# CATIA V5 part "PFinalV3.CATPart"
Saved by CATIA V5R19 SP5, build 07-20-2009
Part number: PeçaFinal
Bounding box of the stored display mesh (mm): x -39 to 2, y -77 to 65.5, z -65.329 to 80.065
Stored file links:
  Z:\UA\ATLAS\atlascar\ServoPiloto\dir\suportePotenciometro\V2\PFinalV3.CATPart
  Z:\UA\ATLAS\atlascar\ServoPiloto\dir\PFinalV3.CATPart
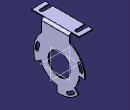
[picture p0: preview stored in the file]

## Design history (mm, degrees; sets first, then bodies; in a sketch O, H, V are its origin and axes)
SheetMetalParameters1: Thickness 2, BendRadius 4, KFactor 0.400515 {= log(min(100,max(20*SheetMetalParameters1.BendRadius,SheetMetalParameters1.Thickness)/SheetMetalParameters1.Thickness))/log(100)/2}, ReliefRadialLength 1, ReliefAxialLength 2, MinimumBendRadius 0
Body1 (main body)
  Sketch1 on yz-plane, origin (0, 0, 0), H (0, 1, 0), V (0, 0, 1)
    circle A1 centre (0, 0) radius 28.5
    circle A2 centre (0, 0) radius 65.5
    construction circle A3 centre (0, 0) radius 57.5
    construction line L1 (0, 0) -> (102.6508, 37.3618)
    point P1 (0, 0)
    construction line L2 (0, 0) -> (-87.8315, 20.2775)
    construction line L3 (0, 0) -> (59.7099, -95.5558)
    construction arc A4 centre (0, 0) radius 57.5 from (56.2235, 12.0488) to (51.1939, 26.1808) ccw
    point P5 (51.1939, 26.1808)
    point P6 (56.2235, 12.0488)
    arc A5 centre (56.2235, 12.0488) radius 4 from (60.1347, 12.8869) to (52.3123, 11.2106) cw
    arc A6 centre (51.1939, 26.1808) radius 4 from (47.6326, 24.3595) to (54.7552, 28.0021) cw
    arc A7 centre (0, 0) radius 53.5 from (52.3123, 11.2106) to (47.6326, 24.3595) ccw
    arc A8 centre (0, 0) radius 61.5 from (54.7552, 28.0021) to (60.1347, 12.8869) cw
    construction arc A9 centre (0, 0) radius 57.5 from (-54.2431, 19.0772) to (-57.3315, 4.3986) ccw
    point P11 (-54.2431, 19.0772)
    point P12 (-57.3315, 4.3986)
    arc A10 centre (-54.2431, 19.0772) radius 4 from (-58.0165, 20.4043) to (-50.4696, 17.7501) cw
    arc A11 centre (-57.3315, 4.3986) radius 4 from (-53.3432, 4.0926) to (-61.3198, 4.7046) cw
    arc A12 centre (0, 0) radius 53.5 from (-50.4696, 17.7501) to (-53.3432, 4.0926) ccw
    arc A13 centre (0, 0) radius 61.5 from (-61.3198, 4.7046) to (-58.0165, 20.4043) cw
    construction arc A14 centre (0, 0) radius 57.5 from (22.6644, -52.8448) to (35.5611, -45.1847) ccw
    point P17 (22.6644, -52.8448)
    point P18 (35.5611, -45.1847)
    arc A15 centre (22.6644, -52.8448) radius 4 from (24.2411, -56.521) to (21.0878, -49.1687) cw
    arc A16 centre (35.5611, -45.1847) radius 4 from (33.0872, -42.0415) to (38.0349, -48.328) cw
    arc A17 centre (0, 0) radius 53.5 from (21.0878, -49.1687) to (33.0872, -42.0415) ccw
    arc A18 centre (0, 0) radius 61.5 from (38.0349, -48.328) to (24.2411, -56.521) cw
    radius A1 = 28.5
    radius A2 = 65.5
    radius A3 = 57.5
    angle L1 H = 20
    angle H L2 = 13
    radius A6 = 4
    radius A11 = 4
    radius A16 = 4
    distance L2 P11 = 6.3862
    distance P12 L2 = 8.6109
    distance L1 P5 = 7.0926
    distance P6 L1 = 7.9074
    distance L3 P18 = 6.2132
    distance P17 L3 = 8.783
    angle H L3 = 58
    coincidence: P1 H, P5 A3, P11 A3, P17 A3, P1 O
    tangency: A7 A6, A6 A8, A8 A5, A5 A7, A12 A11, A11 A13, A13 A10, A10 A12, A17 A16, A16 A18, A18 A15, A15 A17
    concentricity: A7 O, A8 O, A12 O, A13 O, A17 O, A18 O
  Pad1: profile Sketch1, direction (1, 0, 0), length 2
  Sketch2 on end face of Pad1, origin (2, 0, 0), H (0, 1, 0), V (0, 0, 1)
    line L1 (-45, 109.0648) -> (26, 109.0648)
    line L2 (26, 109.0648) -> (26, 29.0648)
    line L3 (26, 29.0648) -> (-45, 29.0648)
    line L4 (-45, 29.0648) -> (-45, 109.0648)
    distance H L3 = 29.0648
    length L2 = 80
    distance V L2 = 26
    distance V L4 = 45
    horizontal: L1 H, L3 H
    vertical: L2 V, L4 V
  Pad2: profile Sketch2, direction (1, 0, 0), up to start face of Pad1
  Sketch3 on face of Pad2 from Sketch2.L4, origin (0, -45, 0), H (1, 0, 0), V (0, 0, 1)
    line L1 (0, 74.0648) -> (0, 109.0648)
    line L2 (0, 109.0648) -> (2, 109.0648)
    line L3 (2, 109.0648) -> (2, 74.0648)
    line L4 (0, 74.0648) -> (2, 74.0648)
    distance L2 L4 = 35
    distance H L4 = 74.0648
    length L2 = 2
    distance L1 V = 0
    horizontal: L4 H
    vertical: L3 V
  Pad3: profile Sketch3, direction (0, -1, 0), length 28, opposite side length 100
  Sketch4 on face of Pad3, origin (2, 0, 0), H (0, 1, 0), V (0, 0, 1)
    arc A1 centre (29, 87.0648) radius 4.5 from (24.5, 87.0648) to (33.5, 87.0648) ccw
    point P1 (29, 87.0648)
    arc A2 centre (-53, 87.0648) radius 4.5 from (-57.5, 87.0648) to (-48.5, 87.0648) ccw
    point P2 (-53, 87.0648)
    reference projected line E1 (26, 109.0648) -> (-45, 109.0648) from edge [face of Pad3 | face of Pad3]
    reference projected line E2 (26, 109.0648) -> (-45, 109.0648) from edge [face of Pad3 | face of Pad3]
    line L1 (33.5, 87.0648) -> (33.5, 115.8082)
    point P3 (33.5, 87.0648)
    line L2 (24.5, 87.0648) -> (24.5, 115.8082)
    point P5 (24.5, 87.0648)
    line L3 (-48.5, 87.0648) -> (-48.5, 115.8082)
    point P7 (-48.5, 87.0648)
    line L4 (-57.5, 87.0648) -> (-57.5, 115.8082)
    point P9 (-57.5, 87.0648)
    line L5 (24.5, 115.8082) -> (33.5, 115.8082)
    line L6 (-57.5, 115.8082) -> (-48.5, 115.8082)
    point P11 (24.5, 87.0648)
    point P12 (33.5, 87.0648)
    point P13 (-57.5, 87.0648)
    point P14 (-48.5, 87.0648)
    radius A2 = 4.5
    radius A1 = 4.5
    distance P2 E1 = 22
    distance P1 E2 = 22
    distance V P1 = 29
    distance P2 P1 = 82
    coincidence: P3 A1, P5 A1, P7 A2, P9 A2, L1 P12, L2 P11, L3 P14, L4 P13, P3 P12, P5 P11, P7 P14, P9 P13
    tangency: L1 A1, L2 A1, L3 A2, L4 A2
    horizontal: L5 H, L6 H
  Pocket1: profile Sketch4, direction (-1, 0, 0), through (limit type 3)
  Split1: SplitPlane face of Pad3 from Sketch3.L4
  Recognize1: Recognize_BendTable SheetMetalParameters1, Recognize_ReferenceFace face of Pad3, KFacteur 0.400515 {= SheetMetalParameters1.KFactor}
  Flange1: Angle 90, Length 35, Radius 4, KFacteur 0.400515 {= log(min(100,max(20*Flange1.Radius,SheetMetalParameters1.Thickness)/SheetMetalParameters1.Thickness))/log(100)/2}, Guide edge [face of Recognize1 | face of Recognize1]
  Sketch5 on face of Flange1, origin (0, -45, 0), H (1, 0, 0), V (0, 0, 1)
    line L1 (-4, 78.0648) -> (-39, 78.0648)
    line L2 (-39, 78.0648) -> (-39, 80.0648)
    line L3 (-39, 80.0648) -> (-4, 80.0648)
    line L4 (-4, 78.0648) -> (-4, 80.0648)
    reference projected line E1 (-4, 80.0648) -> (-39, 80.0648) from edge [face of Flange1 | face of Flange1]
    reference projected line E2 (-4, 78.0648) -> (-39, 78.0648) from edge [face of Flange1 | face of Flange1]
    reference intersected line E3 (-39, 78.0648) -> (-39, 80.0648) from face of Flange1
    distance L2 L4 = 35
    horizontal: L3 H
    coincidence: L3 E1, L1 E2, L2 E3
  Pad4: profile Sketch5, direction (0, -1, 0), length 32, opposite side length 90
  Sketch6 on face of Pad4, origin (-74.0648, 0, 78.0648), H (0, 1, 0), V (1, 0, 0)
    arc A1 centre (-62, 59.0648) radius 4.5 from (-57.5, 59.0648) to (-66.5, 59.0648) ccw
    point P1 (-62, 59.0648)
    arc A2 centre (29, 59.0648) radius 4.5 from (33.5, 59.0648) to (24.5, 59.0648) ccw
    point P2 (29, 59.0648)
    line L1 (-66.5, 59.0648) -> (-66.5, 30.3215)
    point P3 (-66.5, 59.0648)
    line L2 (-57.5, 59.0648) -> (-57.5, 30.3215)
    point P5 (-57.5, 59.0648)
    line L3 (24.5, 59.0648) -> (24.5, 35.0648)
    point P7 (24.5, 59.0648)
    line L4 (33.5, 59.0648) -> (33.5, 35.0648)
    point P9 (33.5, 59.0648)
    line L5 (-57.5, 30.3215) -> (-66.5, 30.3215)
    line L6 (33.5, 35.0648) -> (24.5, 35.0648)
    point P11 (-57.5, 59.0648)
    point P12 (-66.5, 59.0648)
    point P13 (33.5, 59.0648)
    point P14 (24.5, 59.0648)
    reference projected line E1 (26, 35.0648) -> (-45, 35.0648) from edge [face of Pad4 | face of Pad4]
    radius A2 = 4.5
    radius A1 = 4.5
    distance P2 P1 = 91
    length L3 = 24
    distance P2 V = 29
    coincidence: P3 A1, P5 A1, P7 A2, P9 A2, L1 P12, L2 P11, L3 P14, L4 P13, P3 P12, P5 P11, P7 P14, P9 P13, L6 E1
    tangency: L1 A1, L2 A1, L3 A2, L4 A2
    vertical: L3 V, L4 V
  Pocket2: profile Sketch6, direction (0, 0, 1), through (limit type 3)
  Sketch7 on face of Recognize1, origin (0, 0, 0), H (0, -1, 0), V (0, 0, 1)
    arc A1 centre (0, 0) radius 49.0455 from (4.724, -48.8175) to (46.8718, -14.4394) ccw
    line L1 (46.8718, -14.4394) -> (81.591, -37.4888)
    line L2 (81.591, -37.4888) -> (4.724, -86.9825)
    line L3 (4.724, -86.9825) -> (4.724, -48.8175)
    arc A2 centre (0, 0) radius 50.5673 from (-50.5547, -1.131) to (-38.7521, -32.4858) ccw
    line L4 (-50.5547, -1.131) -> (-91.49, -1.131)
    line L5 (-91.49, -1.131) -> (-66.8429, -63.7544)
    line L6 (-66.8429, -63.7544) -> (-38.7521, -32.4858)
    vertical: L3 V
    horizontal: L4 H
  Pocket3: profile Sketch7, direction (1, 0, 0), through (limit type 3)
